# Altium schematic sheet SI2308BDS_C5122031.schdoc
size 127 x 101 mm
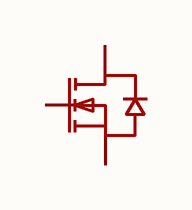
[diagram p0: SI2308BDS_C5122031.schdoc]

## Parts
Q?  si2308bds  [SOT-23-3_L2.9-W1.3-P1.90-LS2.4-BR]  (value not drawn)

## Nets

Not connected (* = marked no-connect by the designer): Q? 1(G) 2(S) 3(D)

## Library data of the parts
Q? = si2308bds: 数量:1个N沟道;漏源电压(Vdss):60V;连续漏极电流(Id):3A;导通电阻(RDS(on)):105mΩ@10V;耗散功率(Pd):350mW;阈值电压(Vgs(th)):2V;; Manufacturer: TECH PUBLIC(台舟); Symbol: SI2308BDS_C5122031; AddInBom: yes; ModelId: c62791f0466c4ae2a892c056b845b0ca; ModelName: SOT-23-3P_L2.9-W1.3-H1.0-LS2.4-P0.95; ModelTransform: 98.425,114.173,0,180,0,0,0.0005,-0.0005,0; Number: 1个N沟道; Drain to Source Voltage: 60V; Current - Continuous Drain(Id): 3A; Pd - Power Dissipation: 350mW; Gate Threshold Voltage (Vgs(th)): 2V; Gate Charge(Qg): 6nC@4.5V; Input Capacitance(Ciss): 247pF; Reverse Transfer Capacitance (Crss@Vds): 19.5pF; Type: N沟道; Output Capacitance(Coss): 34pF; Vgs: ±20V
